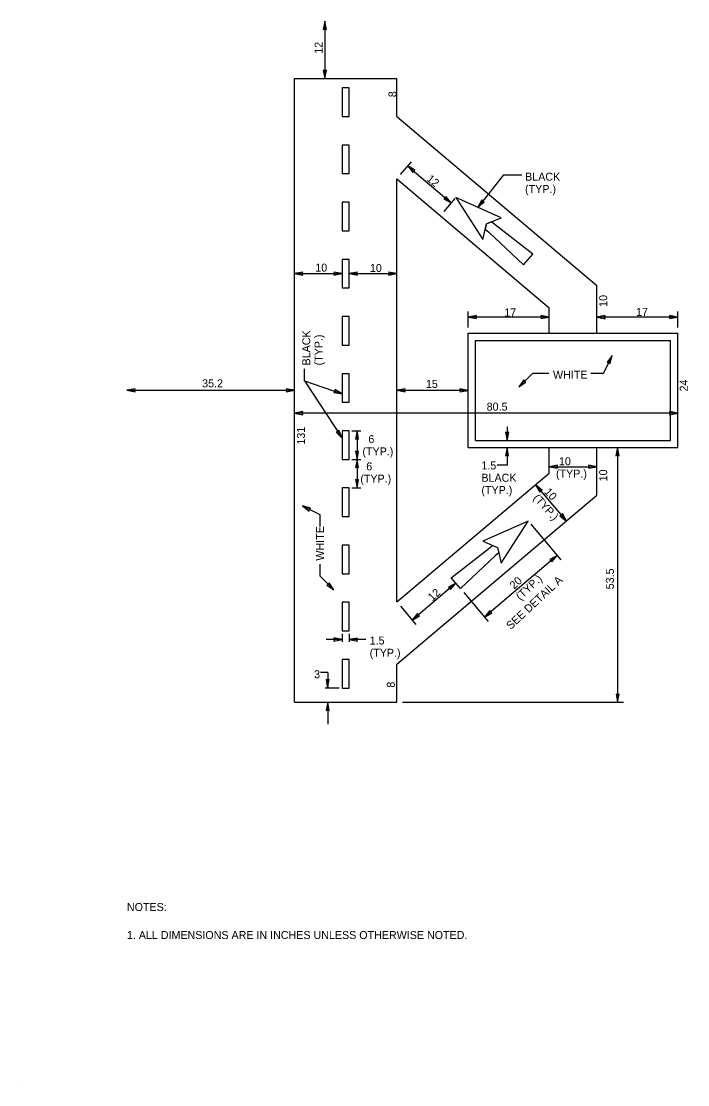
# Model space of a CAD drawing. Extents: x 319706 to 320019, y 1621790 to 1621976.
# Drawn here: x 319705.9 to 319822.6, y 1621790 to 1621976.1 of the extents above; entities that cross this region are included whole.
import ezdxf

# ---------------------------------------------------------------- set-up
doc = ezdxf.new("R2010")
doc.units = 0
for name, color, linetype in [('1', 7, 'Continuous'), ('40', 7, 'Continuous'), ('48', 7, 'Continuous'), ('52', 7, 'Continuous'), ('AdhocPoint_dp', 7, 'Continuous'), ('TextNotes', 7, 'Continuous')]:
    doc.layers.add(name, color=color, linetype=linetype)

msp = doc.modelspace()

# ---------------------------------------------------------------- linework, layer by layer
at = {"layer": '1'}
for p, q in [((319753.72, 1621856.96), (319753.72, 1621966.12)), ((319753.72, 1621966.12), (319771.64, 1621966.12)), ((319771.64, 1621959.46), (319771.64, 1621966.12)), ((319771.64, 1621959.46), (319806.64, 1621929.87)), ((319771.64, 1621948.55), (319798.3, 1621926.01)), ((319771.64, 1621874.54), (319771.64, 1621948.55)), ((319806.64, 1621921.54), (319806.64, 1621929.87)), ((319798.3, 1621921.54), (319798.3, 1621926.01)), ((319784.14, 1621921.54), (319820.8, 1621921.54)), ((319784.14, 1621901.54), (319784.14, 1621921.54)), ((319820.8, 1621901.54), (319820.8, 1621921.54)), ((319785.39, 1621920.29), (319819.55, 1621920.29)), ((319785.39, 1621902.79), (319785.39, 1621920.29)), ((319819.55, 1621902.79), (319819.55, 1621920.29)), ((319785.39, 1621902.79), (319819.55, 1621902.79)), ((319784.14, 1621901.54), (319820.8, 1621901.54)), ((319798.3, 1621897.08), (319798.3, 1621901.54)), ((319806.64, 1621893.21), (319806.64, 1621901.54)), ((319771.64, 1621874.54), (319798.3, 1621897.08)), ((319771.64, 1621863.62), (319806.64, 1621893.21)), ((319771.64, 1621856.96), (319771.64, 1621863.62)), ((319753.72, 1621856.96), (319771.64, 1621856.96))]:
    msp.add_line(p, q, dxfattribs=at)
at = {"layer": '40'}
for p, q in [((319763.3, 1621964.46), (319762.05, 1621964.46)), ((319762.05, 1621964.46), (319762.05, 1621959.46)), ((319763.3, 1621959.46), (319763.3, 1621964.46)), ((319762.05, 1621959.46), (319763.3, 1621959.46)), ((319763.3, 1621954.46), (319762.05, 1621954.46)), ((319762.05, 1621954.46), (319762.05, 1621949.46)), ((319763.3, 1621949.46), (319763.3, 1621954.46)), ((319762.05, 1621949.46), (319763.3, 1621949.46)), ((319781.96, 1621945.27), (319786.66, 1621937.95)), ((319789.92, 1621941.75), (319781.96, 1621945.27)), ((319763.3, 1621944.46), (319762.05, 1621944.46)), ((319762.05, 1621944.46), (319762.05, 1621939.46)), ((319763.3, 1621939.46), (319763.3, 1621944.46)), ((319787.34, 1621940.66), (319789.92, 1621941.75)), ((319786.66, 1621937.95), (319787.34, 1621940.66)), ((319787.34, 1621940.66), (319787.12, 1621939.76)), ((319787.12, 1621939.76), (319787.75, 1621939.22)), ((319788.2, 1621941.03), (319787.34, 1621940.66)), ((319788.83, 1621940.48), (319788.2, 1621941.03)), ((319795.43, 1621935.38), (319788.83, 1621940.48)), ((319762.05, 1621939.46), (319763.3, 1621939.46)), ((319787.75, 1621939.22), (319793.8, 1621933.48)), ((319763.3, 1621934.46), (319762.05, 1621934.46)), ((319762.05, 1621934.46), (319762.05, 1621929.46)), ((319763.3, 1621929.46), (319763.3, 1621934.46)), ((319793.8, 1621933.48), (319795.43, 1621935.38)), ((319762.05, 1621929.46), (319763.3, 1621929.46)), ((319763.3, 1621924.46), (319762.05, 1621924.46)), ((319762.05, 1621924.46), (319762.05, 1621919.46)), ((319763.3, 1621919.46), (319763.3, 1621924.46)), ((319762.05, 1621919.46), (319763.3, 1621919.46)), ((319763.3, 1621914.46), (319762.05, 1621914.46)), ((319762.05, 1621914.46), (319762.05, 1621909.46)), ((319763.3, 1621909.46), (319763.3, 1621914.46)), ((319762.05, 1621909.46), (319763.3, 1621909.46)), ((319763.3, 1621904.46), (319762.05, 1621904.46)), ((319762.05, 1621904.46), (319762.05, 1621899.46)), ((319763.3, 1621899.46), (319763.3, 1621904.46)), ((319762.05, 1621899.46), (319763.3, 1621899.46)), ((319763.3, 1621894.46), (319762.05, 1621894.46)), ((319762.05, 1621894.46), (319762.05, 1621889.46)), ((319763.3, 1621889.46), (319763.3, 1621894.46)), ((319762.05, 1621889.46), (319763.3, 1621889.46)), ((319794.62, 1621888.66), (319786.66, 1621885.13)), ((319789.92, 1621881.33), (319794.62, 1621888.66)), ((319763.3, 1621884.46), (319762.05, 1621884.46)), ((319762.05, 1621884.46), (319762.05, 1621879.46)), ((319763.3, 1621879.46), (319763.3, 1621884.46)), ((319781.15, 1621878.76), (319787.75, 1621883.87)), ((319786.66, 1621885.13), (319789.24, 1621884.05)), ((319787.75, 1621883.87), (319788.38, 1621884.41)), ((319788.38, 1621884.41), (319789.24, 1621884.05)), ((319789.24, 1621884.05), (319789.92, 1621881.33)), ((319789.24, 1621884.05), (319789.47, 1621883.14)), ((319788.83, 1621882.6), (319782.78, 1621876.86)), ((319789.47, 1621883.14), (319788.83, 1621882.6)), ((319762.05, 1621879.46), (319763.3, 1621879.46)), ((319782.78, 1621876.86), (319781.15, 1621878.76)), ((319763.3, 1621874.46), (319762.05, 1621874.46)), ((319762.05, 1621874.46), (319762.05, 1621869.46)), ((319763.3, 1621869.46), (319763.3, 1621874.46)), ((319762.05, 1621869.46), (319763.3, 1621869.46)), ((319763.3, 1621864.46), (319762.05, 1621864.46)), ((319762.05, 1621864.46), (319762.05, 1621859.46)), ((319763.3, 1621859.46), (319763.3, 1621864.46)), ((319762.05, 1621859.46), (319763.3, 1621859.46))]:
    msp.add_line(p, q, dxfattribs=at)
at = {"layer": '48'}
for p, q in [((319759.04, 1621976.12), (319759.04, 1621966.13)), ((319772.28, 1621949.31), (319774.18, 1621951.55)), ((319773.53, 1621950.79), (319781.17, 1621944.34)), ((319790.32, 1621949.23), (319785.83, 1621943.56)), ((319790.32, 1621949.23), (319793.54, 1621949.23)), ((319779.92, 1621942.86), (319781.82, 1621945.1)), ((319762.05, 1621931.96), (319753.72, 1621931.96)), ((319771.64, 1621931.96), (319763.3, 1621931.96)), ((319784.14, 1621922.56), (319784.14, 1621925.36)), ((319820.8, 1621922.56), (319820.8, 1621925.36)), ((319798.3, 1621924.36), (319784.14, 1621924.36)), ((319820.8, 1621924.36), (319806.64, 1621924.36)), ((319807.83, 1621914.53), (319809.37, 1621917.64)), ((319755.47, 1621913.22), (319755.47, 1621915.29)), ((319795.44, 1621914.53), (319793.02, 1621912.14)), ((319795.44, 1621914.53), (319798.25, 1621914.53)), ((319805.61, 1621914.53), (319807.83, 1621914.53)), ((319755.47, 1621913.22), (319762.05, 1621910.92)), ((319755.47, 1621913.22), (319762.05, 1621903.17)), ((319753.72, 1621911.54), (319724.39, 1621911.54)), ((319784.14, 1621911.54), (319771.64, 1621911.54)), ((319820.8, 1621907.55), (319753.72, 1621907.55)), ((319763.76, 1621904.46), (319765.33, 1621904.46)), ((319764.67, 1621904.46), (319764.67, 1621899.46)), ((319790.95, 1621905.16), (319790.95, 1621902.79)), ((319790.95, 1621901.54), (319790.95, 1621898.43)), ((319810.29, 1621901.54), (319810.29, 1621856.96)), ((319763.76, 1621899.46), (319765.33, 1621899.46)), ((319764.67, 1621899.46), (319764.67, 1621894.46)), ((319790.95, 1621898.43), (319789.22, 1621898.43)), ((319798.3, 1621898.17), (319806.64, 1621898.17)), ((319763.76, 1621894.46), (319765.33, 1621894.46)), ((319795.92, 1621895), (319801.35, 1621888.67)), ((319758.23, 1621889.78), (319755.12, 1621891.32)), ((319758.23, 1621887.7), (319758.23, 1621889.78)), ((319795.08, 1621888.11), (319800.35, 1621881.88)), ((319799.7, 1621882.64), (319786.98, 1621871.87)), ((319758.23, 1621879.04), (319758.23, 1621881.12)), ((319758.23, 1621879.04), (319760.62, 1621876.63)), ((319781.96, 1621877.81), (319774.33, 1621871.35)), ((319783.36, 1621876.16), (319787.63, 1621871.11)), ((319772.28, 1621873.77), (319774.98, 1621870.58)), ((319762.05, 1621867.92), (319759.25, 1621867.92)), ((319762.05, 1621868.96), (319762.05, 1621867.54)), ((319763.3, 1621868.96), (319763.3, 1621867.54)), ((319766.18, 1621867.92), (319763.3, 1621867.92)), ((319759.53, 1621862.18), (319758.26, 1621862.18)), ((319759.53, 1621862.18), (319759.53, 1621859.46)), ((319761.51, 1621859.46), (319759.11, 1621859.46)), ((319759.53, 1621856.96), (319759.53, 1621853.14)), ((319772.64, 1621856.96), (319811.29, 1621856.96))]:
    msp.add_line(p, q, dxfattribs=at)
at = {"layer": '52'}
for p, q in [((319759.04, 1621976.12), (319758.76, 1621974.67)), ((319759.31, 1621974.67), (319759.04, 1621976.12)), ((319758.76, 1621974.67), (319759.04, 1621974.78)), ((319759.04, 1621974.78), (319759.31, 1621974.67)), ((319759.03, 1621967.46), (319758.76, 1621967.57)), ((319758.76, 1621967.57), (319759.03, 1621966.12)), ((319759.03, 1621966.12), (319759.31, 1621967.57)), ((319759.31, 1621967.57), (319759.03, 1621967.46)), ((319773.53, 1621950.8), (319774.45, 1621949.65)), ((319774.81, 1621950.07), (319773.53, 1621950.8)), ((319774.45, 1621949.65), (319774.55, 1621949.93)), ((319774.55, 1621949.93), (319774.81, 1621950.07)), ((319780.24, 1621945.49), (319780.14, 1621945.21)), ((319781.16, 1621944.34), (319780.24, 1621945.49)), ((319780.14, 1621945.21), (319779.88, 1621945.07)), ((319779.88, 1621945.07), (319781.16, 1621944.34)), ((319786.51, 1621944.87), (319785.83, 1621943.57)), ((319785.83, 1621943.57), (319786.95, 1621944.53)), ((319786.66, 1621944.62), (319786.51, 1621944.87)), ((319786.95, 1621944.53), (319786.66, 1621944.62)), ((319755.17, 1621932.24), (319753.72, 1621931.97)), ((319755.06, 1621931.97), (319755.17, 1621932.24)), ((319762.05, 1621931.97), (319760.6, 1621932.25)), ((319760.6, 1621932.25), (319760.71, 1621931.97)), ((319764.75, 1621932.24), (319763.3, 1621931.97)), ((319764.64, 1621931.97), (319764.75, 1621932.24)), ((319771.63, 1621931.97), (319770.18, 1621932.25)), ((319770.18, 1621932.25), (319770.29, 1621931.97)), ((319753.72, 1621931.97), (319755.17, 1621931.69)), ((319755.17, 1621931.69), (319755.06, 1621931.97)), ((319760.71, 1621931.97), (319760.6, 1621931.7)), ((319760.6, 1621931.7), (319762.05, 1621931.97)), ((319763.3, 1621931.97), (319764.75, 1621931.69)), ((319764.75, 1621931.69), (319764.64, 1621931.97)), ((319770.29, 1621931.97), (319770.18, 1621931.7)), ((319770.18, 1621931.7), (319771.63, 1621931.97)), ((319785.58, 1621924.64), (319784.13, 1621924.37)), ((319784.13, 1621924.37), (319785.58, 1621924.09)), ((319785.47, 1621924.37), (319785.58, 1621924.64)), ((319785.58, 1621924.09), (319785.47, 1621924.37)), ((319798.3, 1621924.36), (319796.85, 1621924.64)), ((319796.85, 1621924.64), (319796.96, 1621924.36)), ((319796.96, 1621924.36), (319796.85, 1621924.09)), ((319796.85, 1621924.09), (319798.3, 1621924.36)), ((319808.08, 1621924.63), (319806.63, 1621924.36)), ((319806.63, 1621924.36), (319808.08, 1621924.08)), ((319807.97, 1621924.36), (319808.08, 1621924.63)), ((319808.08, 1621924.08), (319807.97, 1621924.36)), ((319820.8, 1621924.37), (319819.35, 1621924.65)), ((319819.35, 1621924.65), (319819.46, 1621924.37)), ((319819.46, 1621924.37), (319819.35, 1621924.1)), ((319819.35, 1621924.1), (319820.8, 1621924.37)), ((319809.36, 1621917.64), (319808.46, 1621916.47)), ((319808.96, 1621916.23), (319809.36, 1621917.64)), ((319808.46, 1621916.47), (319808.76, 1621916.44)), ((319808.76, 1621916.44), (319808.96, 1621916.23)), ((319725.83, 1621911.82), (319724.38, 1621911.55)), ((319725.72, 1621911.55), (319725.83, 1621911.82)), ((319753.71, 1621911.55), (319752.26, 1621911.83)), ((319752.26, 1621911.83), (319752.37, 1621911.55)), ((319773.08, 1621911.82), (319771.63, 1621911.55)), ((319772.97, 1621911.55), (319773.08, 1621911.82)), ((319784.13, 1621911.54), (319782.68, 1621911.82)), ((319782.68, 1621911.82), (319782.79, 1621911.54)), ((319793.85, 1621913.36), (319793.01, 1621912.14)), ((319793.01, 1621912.14), (319794.24, 1621912.96)), ((319793.96, 1621913.09), (319793.85, 1621913.36)), ((319794.24, 1621912.96), (319793.96, 1621913.09)), ((319724.38, 1621911.55), (319725.83, 1621911.27)), ((319725.83, 1621911.27), (319725.72, 1621911.55)), ((319752.37, 1621911.55), (319752.26, 1621911.28)), ((319752.26, 1621911.28), (319753.71, 1621911.55)), ((319760.78, 1621911.37), (319760.59, 1621911.15)), ((319760.59, 1621911.15), (319762.05, 1621910.93)), ((319762.05, 1621910.93), (319760.77, 1621911.67)), ((319760.77, 1621911.67), (319760.78, 1621911.37)), ((319771.63, 1621911.55), (319773.08, 1621911.27)), ((319773.08, 1621911.27), (319772.97, 1621911.55)), ((319782.79, 1621911.54), (319782.68, 1621911.27)), ((319782.68, 1621911.27), (319784.13, 1621911.54)), ((319755.17, 1621907.83), (319753.72, 1621907.56)), ((319753.72, 1621907.56), (319755.17, 1621907.28)), ((319755.06, 1621907.56), (319755.17, 1621907.83)), ((319755.17, 1621907.28), (319755.06, 1621907.56)), ((319820.8, 1621907.55), (319819.35, 1621907.83)), ((319819.35, 1621907.83), (319819.46, 1621907.55)), ((319819.46, 1621907.55), (319819.35, 1621907.28)), ((319819.35, 1621907.28), (319820.8, 1621907.55)), ((319761.49, 1621904.55), (319761.32, 1621904.3)), ((319762.05, 1621903.18), (319761.49, 1621904.55)), ((319764.67, 1621904.47), (319764.39, 1621903.02)), ((319764.94, 1621903.02), (319764.67, 1621904.47)), ((319761.32, 1621904.3), (319761.03, 1621904.25)), ((319761.03, 1621904.25), (319762.05, 1621903.18)), ((319764.39, 1621903.02), (319764.67, 1621903.13)), ((319764.67, 1621903.13), (319764.94, 1621903.02)), ((319790.94, 1621904.13), (319790.67, 1621904.24)), ((319790.67, 1621904.24), (319790.94, 1621902.79)), ((319790.94, 1621902.79), (319791.22, 1621904.24)), ((319791.22, 1621904.24), (319790.94, 1621904.13)), ((319764.67, 1621900.81), (319764.4, 1621900.92)), ((319764.4, 1621900.92), (319764.67, 1621899.47)), ((319764.67, 1621899.47), (319764.95, 1621900.92)), ((319764.95, 1621900.92), (319764.67, 1621900.81)), ((319790.94, 1621901.55), (319790.66, 1621900.1)), ((319791.21, 1621900.1), (319790.94, 1621901.55)), ((319810.28, 1621901.55), (319810, 1621900.1)), ((319810.55, 1621900.1), (319810.28, 1621901.55)), ((319764.67, 1621899.47), (319764.39, 1621898.02)), ((319764.94, 1621898.02), (319764.67, 1621899.47)), ((319790.66, 1621900.1), (319790.94, 1621900.21)), ((319790.94, 1621900.21), (319791.21, 1621900.1)), ((319810, 1621900.1), (319810.28, 1621900.21)), ((319810.28, 1621900.21), (319810.55, 1621900.1)), ((319764.39, 1621898.02), (319764.67, 1621898.13)), ((319764.67, 1621898.13), (319764.94, 1621898.02)), ((319799.75, 1621898.45), (319798.3, 1621898.18)), ((319798.3, 1621898.18), (319799.75, 1621897.9)), ((319799.64, 1621898.18), (319799.75, 1621898.45)), ((319799.75, 1621897.9), (319799.64, 1621898.18)), ((319806.63, 1621898.18), (319805.18, 1621898.46)), ((319805.18, 1621898.46), (319805.29, 1621898.18)), ((319805.29, 1621898.18), (319805.18, 1621897.91)), ((319805.18, 1621897.91), (319806.63, 1621898.18)), ((319764.67, 1621895.81), (319764.4, 1621895.92)), ((319764.4, 1621895.92), (319764.67, 1621894.47)), ((319764.67, 1621894.47), (319764.95, 1621895.92)), ((319764.95, 1621895.92), (319764.67, 1621895.81)), ((319795.92, 1621895.01), (319796.65, 1621893.73)), ((319797.07, 1621894.09), (319795.92, 1621895.01)), ((319796.65, 1621893.73), (319796.79, 1621893.99)), ((319796.79, 1621893.99), (319797.07, 1621894.09)), ((319755.12, 1621891.33), (319756.29, 1621890.43)), ((319756.53, 1621890.93), (319755.12, 1621891.33)), ((319756.29, 1621890.43), (319756.32, 1621890.73)), ((319756.32, 1621890.73), (319756.53, 1621890.93)), ((319800.47, 1621889.7), (319800.19, 1621889.61)), ((319800.19, 1621889.61), (319801.34, 1621888.68)), ((319800.61, 1621889.97), (319800.47, 1621889.7)), ((319801.34, 1621888.68), (319800.61, 1621889.97)), ((319799.69, 1621882.65), (319798.41, 1621881.93)), ((319798.76, 1621881.51), (319799.69, 1621882.65)), ((319798.41, 1621881.93), (319798.67, 1621881.78)), ((319798.67, 1621881.78), (319798.76, 1621881.51)), ((319759.67, 1621877.59), (319759.4, 1621877.48)), ((319759.4, 1621877.48), (319760.62, 1621876.64)), ((319759.8, 1621877.87), (319759.67, 1621877.59)), ((319760.62, 1621876.64), (319759.8, 1621877.87)), ((319781.96, 1621877.82), (319780.67, 1621877.09)), ((319780.67, 1621877.09), (319780.93, 1621876.95)), ((319780.93, 1621876.95), (319781.02, 1621876.67)), ((319781.02, 1621876.67), (319781.96, 1621877.82)), ((319787.91, 1621873.02), (319786.98, 1621871.88)), ((319788, 1621872.74), (319787.91, 1621873.02)), ((319788.26, 1621872.6), (319788, 1621872.74)), ((319775.26, 1621872.5), (319774.33, 1621871.35)), ((319774.33, 1621871.35), (319775.61, 1621872.08)), ((319775.35, 1621872.22), (319775.26, 1621872.5)), ((319775.61, 1621872.08), (319775.35, 1621872.22)), ((319786.98, 1621871.88), (319788.26, 1621872.6)), ((319762.05, 1621867.93), (319760.6, 1621868.21)), ((319760.6, 1621868.21), (319760.71, 1621867.93)), ((319760.71, 1621867.93), (319760.6, 1621867.66)), ((319760.6, 1621867.66), (319762.05, 1621867.93)), ((319764.75, 1621868.2), (319763.3, 1621867.93)), ((319763.3, 1621867.93), (319764.75, 1621867.65)), ((319764.64, 1621867.93), (319764.75, 1621868.2)), ((319764.75, 1621867.65), (319764.64, 1621867.93)), ((319759.52, 1621860.81), (319759.25, 1621860.92)), ((319759.25, 1621860.92), (319759.52, 1621859.47)), ((319759.52, 1621859.47), (319759.8, 1621860.92)), ((319759.8, 1621860.92), (319759.52, 1621860.81)), ((319810.28, 1621858.3), (319810.01, 1621858.41)), ((319810.01, 1621858.41), (319810.28, 1621856.96)), ((319810.28, 1621856.96), (319810.56, 1621858.41)), ((319810.56, 1621858.41), (319810.28, 1621858.3)), ((319759.53, 1621856.96), (319759.25, 1621855.51)), ((319759.8, 1621855.51), (319759.53, 1621856.96)), ((319759.25, 1621855.51), (319759.53, 1621855.62)), ((319759.53, 1621855.62), (319759.8, 1621855.51))]:
    msp.add_line(p, q, dxfattribs=at)
at = {"layer": 'AdhocPoint_dp'}
msp.add_line((319705.88, 1621790.04), (319705.88, 1621790.04), dxfattribs=at)

# ---------------------------------------------------------------- texts
at = {"layer": '48'}
for s, rotation, p in [('12', 90, (319758.65, 1621970.44)), ('8', 90, (319771.57, 1621962.84)), ('12', 321.237, (319776.73, 1621948.33)), ('10', 90, (319808.46, 1621926.15)), ('BLACK', 90, (319756.48, 1621915.9)), ('(TYP.)', 90, (319758.63, 1621915.9)), ('24', 90, (319822.56, 1621911.35)), ('131', 90, (319755.55, 1621902.05)), ('10', 90, (319808.46, 1621895.62)), ('(TYP.)', 312.4213, (319795.41, 1621892.63)), (' 10', 312.4213, (319796.99, 1621894.08)), ('WHITE', 90, (319758.89, 1621881.74)), ('53.5', 90, (319809.63, 1621876.73)), ('SEE DETAIL A', 43.0352, (319791.58, 1621869.59)), (' 20', 43.0352, (319791.79, 1621876.29)), ('(TYP.)', 43.0352, (319793.25, 1621874.72)), ('12', 43.0352, (319777.86, 1621874.58)), ('8', 90, (319771.28, 1621859.52))]:
    msp.add_text(s, height=1.4, rotation=rotation, dxfattribs=at).set_placement(p)
for s, p in [('BLACK', (319794.09, 1621948.23)), ('(TYP.)', (319794.09, 1621946.08)), ('10', (319757.36, 1621932.32)), ('10', (319766.92, 1621932.26)), ('17', (319790.44, 1621924.47)), ('17', (319813.52, 1621924.58)), ('WHITE', (319798.97, 1621913.58)), ('35.2', (319737.55, 1621912.07)), ('15', (319776.72, 1621911.97)), ('80.5', (319787.36, 1621907.99)), ('  6 ', (319765.61, 1621902.31)), ('(TYP.)', (319765.61, 1621900.16)), ('  6 ', (319765.24, 1621897.54)), ('1.5', (319786.44, 1621897.7)), (' 10', (319799.5, 1621898.43)), ('BLACK', (319786.44, 1621895.55)), ('(TYP.)', (319799.5, 1621896.28)), ('(TYP.)', (319765.24, 1621895.39)), ('(TYP.)', (319786.44, 1621893.4)), ('1.5', (319766.88, 1621867.07)), ('(TYP.)', (319766.88, 1621864.92)), ('3', (319757.15, 1621861.17))]:
    msp.add_text(s, height=1.4, dxfattribs=at).set_placement(p)
at = {"layer": 'TextNotes'}
for s, p in [('NOTES:', (319724.38, 1621820.44)), ('1. ALL DIMENSIONS ARE IN INCHES UNLESS OTHERWISE NOTED.', (319724.38, 1621815.54))]:
    msp.add_text(s, height=1.4, dxfattribs=at).set_placement(p)

doc.saveas('drawing.dxf')
